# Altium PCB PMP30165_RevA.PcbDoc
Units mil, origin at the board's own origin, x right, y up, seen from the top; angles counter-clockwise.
Board outline 2445.95 x 1141.73 mil, 2 copper layers (Top Layer, Bottom Layer), stack 62 mil thick; 39 components, 20 nets, 97 pads, 20 vias.
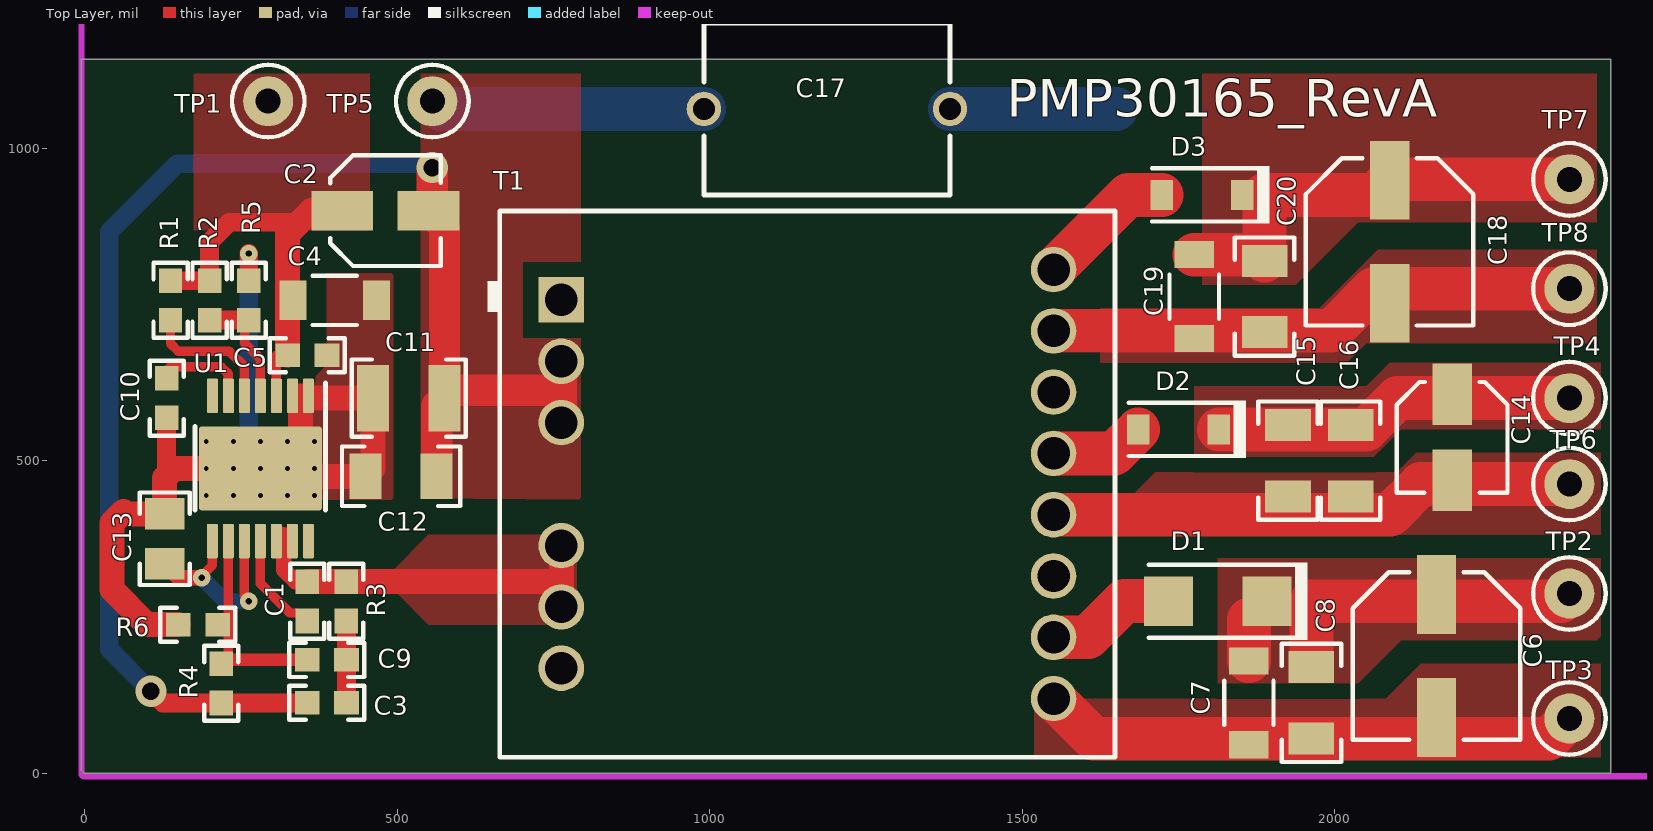
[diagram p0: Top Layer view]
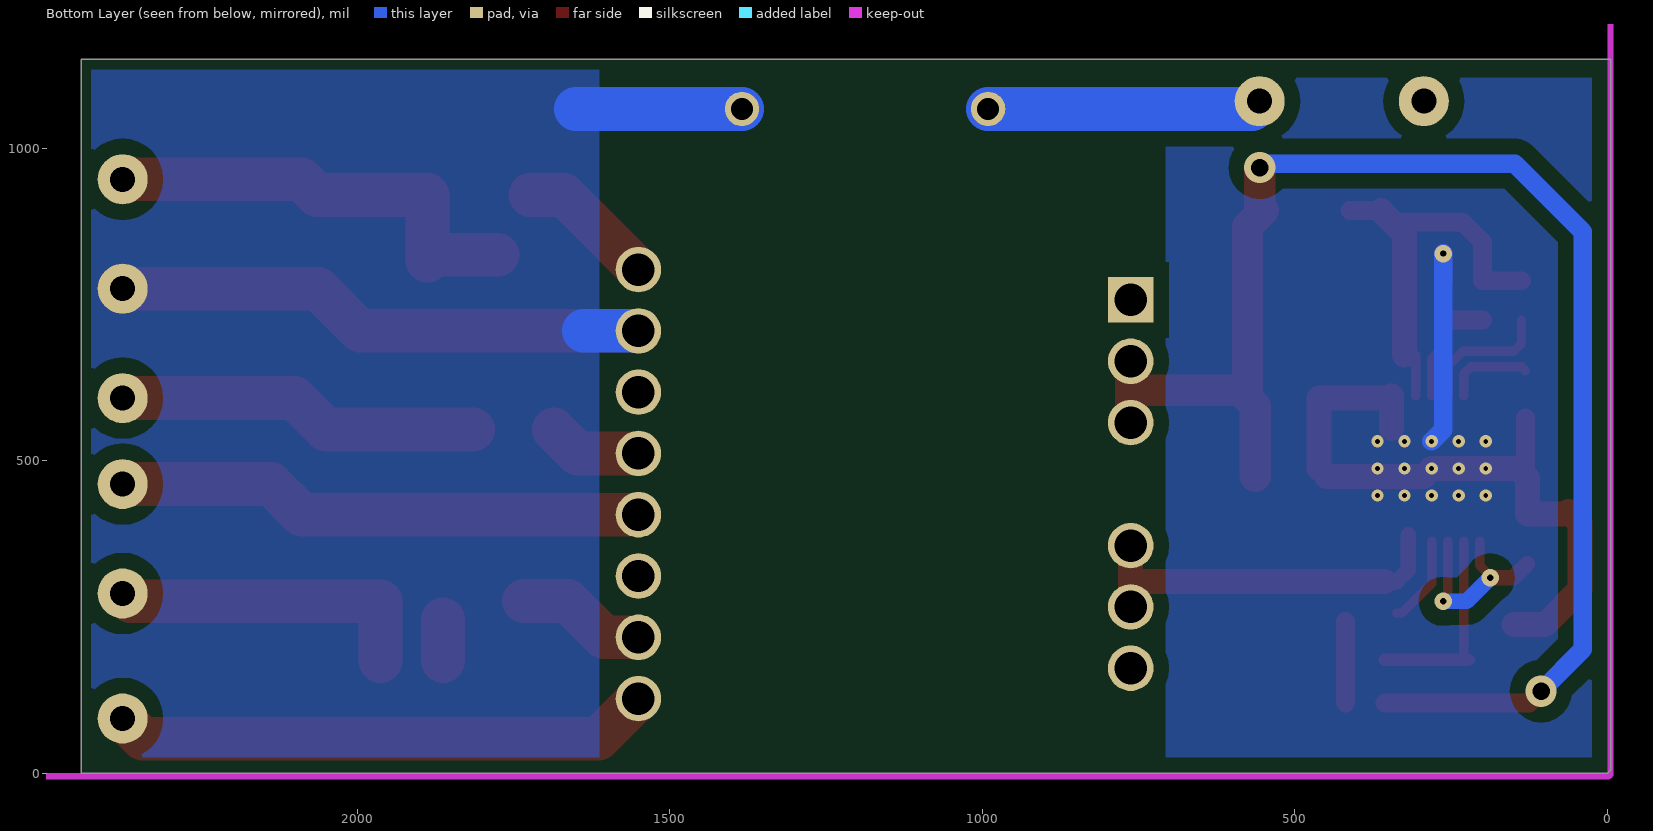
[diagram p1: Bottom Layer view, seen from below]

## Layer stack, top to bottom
Top Solder: solder mask 0.4, Solder Resist, Dk 3.5
Top Layer: signal copper 1.4
Dielectric1: core 59.2, FR-4, Dk 4.8
Bottom Layer: signal copper 1.4
Bottom Solder: solder mask 0.4, Solder Resist, Dk 3.5

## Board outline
0,0 -5,5 -5,1141.73 2440.94,1141.73 2440.94,0

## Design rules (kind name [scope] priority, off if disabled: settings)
AcuteAngle [All] p1: minimum=4.50000000000000E+0001 checktracksonly=FALSE
AssemblyTestPointUsage [All] p1: valid=2
Clearance Clearance_Keepouts [((IsTrack Or IsArc) And Not InPoly) And IsFree and IsKeepOut vs ((IsTrack Or IsArc) And Not InPoly) And IsFree and IsKeepOut] p1: gap=0
Clearance Clearance_BoardEdge_MountingHoles [OnCopper and InComponentClass('Mounting Holes') vs IsKeepOut] p2: gap=20
Clearance Clearance_BoardEdge_Poly [OnCopper and InPoly vs IsKeepOut] p3: gap=25
Clearance Clearance_BoardEdge [OnCopper and Not InComponentClass('Logo') and not InComponentClass('FiducialMark') and not InRegion(1000,500,4000,800) and Not IsKeepout vs IsKeepOut] p4: gap=20
Clearance Clearance_Poly [InPolygon] p5: gap=25
Clearance [All] p6: gap=7.87
ComponentClearance ComponentClearance_MountingHoles_FiducialMarks [InComponentClass('Mounting Holes') vs InComponentClass('FiducialMark')] p1: gap=20 collisioncheckmode=3 verticalgap=10 showdistances=FALSE
ComponentClearance ComponentClearance_Shunt [InComponentClass('Header') vs InComponentClass('Shunt')] p2: gap=0 collisioncheckmode=3 verticalgap=0 showdistances=FALSE
ComponentClearance ComponentClearance_Logo [InComponentClass('Logo')] p3: gap=20 collisioncheckmode=3 verticalgap=10 showdistances=FALSE
ComponentClearance ComponentClearance_ScrewToNut [(HasFootprint('NY PMS 440 0025 PH')) vs (HasFootprint('Keystone_1902C'))] p4: gap=5 collisioncheckmode=3 verticalgap=10 showdistances=FALSE
ComponentClearance ComponentClearance_MountingHoles [InComponentClass('Mounting Holes')] p5: gap=20 collisioncheckmode=3 verticalgap=100000 showdistances=FALSE
ComponentClearance ComponentClearance_SmallPassives [HasFootprint('0201*') or HasFootprint('0402*') or HasFootprint('0508') or HasFootprint('0603*') or HasFootprint('0612') or HasFootprint('0805*') or HasFootprint('0815*') or HasFootprint('0830*') or HasFootprint('1206*') or HasFootprint('1210*') or HasFootprint('1808*') or HasFootprint('1812*') or HasFootprint('1825*') or HasFootprint('2010*') or HasFootprint('2220*') or HasFootprint('2225*') or HasFootprint('2512*') or HasFootprint('2728*') or HasFootprint('3518*') vs HasFootprint('0201*') or HasFootprint('0402*') or HasFootprint('0508') or HasFootprint('0603*') or HasFootprint('0612') or HasFootprint('0805*') or HasFootprint('0815*') or HasFootprint('0830*') or HasFootprint('1206*') or HasFootprint('1210*') or HasFootprint('1808*') or HasFootprint('1812*') or HasFootprint('1825*') or HasFootprint('2010*') or HasFootprint('2220*') or HasFootprint('2225*') or HasFootprint('2512*') or HasFootprint('2728*') or HasFootprint('3518*')] p6: gap=20 collisioncheckmode=3 verticalgap=10 showdistances=FALSE
ComponentClearance ComponentClearance_THtoSMT [IsThruComponent vs IsSMTComponent] p7: gap=20 collisioncheckmode=3 verticalgap=30 showdistances=FALSE
ComponentClearance ComponentClearance_THtoTH [IsThruComponent vs IsThruComponent] p8: gap=20 collisioncheckmode=3 verticalgap=30 showdistances=FALSE
ComponentClearance [All] p9: gap=10 collisioncheckmode=3 verticalgap=10 showdistances=FALSE
DiffPairsRouting [All] p1: maxlimit=100 minlimit=10 mostfreqgap=10 toplayer_minwidth=15 toplayer_maxwidth=15 toplayer_prefwidth=15 bottomlayer_minwidth=15 bottomlayer_maxwidth=15 bottomlayer_prefwidth=15 maxuncoupledlength=1000
FabricationTestPointUsage TestPointUsage [All] p1: valid=2 allowmultiple=FALSE
FabricationTestpoint Testpoint [All] p1: side=3 testpointundercomponent=TRUE minsize=40 maxsize=100 preferedsize=60 minholesize=0 maxholesize=40 preferedholesize=32 testpointgrid=1 allowsidetop=TRUE allowsidebottom=TRUE usegrid=TRUE gridtolerance=0.01
FanoutControl Fanout_LCC [IsLCC] p1: bgadir=Out bgaviamode=Centered fanoutstyle=Auto fanoutdirection=Alternating viagrid=1 // Fanout_LCC (Default Rule)
FanoutControl Fanout_BGA [IsBGA] p2: bgadir=Out bgaviamode=Centered fanoutstyle=Auto fanoutdirection=Alternating viagrid=1 // Fanout_BGA (Default Rule)
FanoutControl Fanout_Default [All] p4: bgadir=Out bgaviamode=Centered fanoutstyle=Auto fanoutdirection=Alternating viagrid=1 // Fanout_Default (Default Rule)
FanoutControl Fanout_Small [(CompPinCount < 5)] p5: bgadir=Out bgaviamode=Centered fanoutstyle=Auto fanoutdirection=OutThenIn viagrid=1 // Fanout_Small (Default Rule)
HoleSize [All] p1: absolutevalues=TRUE maxlimit=251 minlimit=6 maxpercent=80.000 minpercent=20.000
MinimumAnnularRing MinimumAnnularRing_ThermalPadVias [IsVia and InAnyComponent] p1: minimumring=5.91
MinimumAnnularRing [All] p2: minimumring=9
MinimumSolderMaskSliver MinimumSolderMaskSliver_Logo [InComponentClass('Logo') vs InComponentClass('Logo')] p1: minsoldermaskwidth=0.7
MinimumSolderMaskSliver [All] p2: minsoldermaskwidth=3.94
PlaneConnect [All] p1: planeconnectstyle=Relief reliefexpansion=10 reliefentries=4 reliefconductorwidth=10 reliefairgap=10
PolygonConnect [All] p1: connectstyle=Direct reliefconductorwidth=10 reliefentries=4 polygonreliefangle="90 Angle" airgapwidth=10
RoutingVias ThermalPadVias [IsVia and InAnyComponent] p1: holewidth=7.87 width=19.68 viastyle="Through Hole" minholewidth=7.87 minwidth=19.68 maxholewidth=12.99 maxwidth=23.62
RoutingVias [All] p2: holewidth=16 width=34 viastyle="Through Hole" minholewidth=7.87 minwidth=26 maxholewidth=40 maxwidth=65
SilkToBoardRegionClearance [Not ((IsComment or IsDesignator) And (Hide <> 'False')) and not InRegion(1000,500,4000,800)] p1:
SilkToSilkClearance SilkToSilkClearance_Pb-FreeLogo [(HasFootprint('Pb-Free_Overlay_Medium') OR HasFootprint('Pb-Free_Overlay_Small')) vs (HasFootprint('Pb-Free_Overlay_Medium') OR HasFootprint('Pb-Free_Overlay_Small'))] p1: silktosilkclearance=0
SilkToSilkClearance [All] p2: silktosilkclearance=4
SilkToSolderMaskClearance SilkToComonentPadClearance [IsPad and InAnycomponent] p1: minsilkscreentomaskgap=5 clearancetoexposedcopper=TRUE
SilkToSolderMaskClearance "Silk to Solder Mask Opening" [All] p2: minsilkscreentomaskgap=4 clearancetoexposedcopper=FALSE
SolderMaskExpansion [All] p1: expansion=1.97
Width [All] p1: maxlimit=100 minlimit=6 preferedwidth=10 checkconnectedcopper=TRUE
15 further rules are at their usual default settings.

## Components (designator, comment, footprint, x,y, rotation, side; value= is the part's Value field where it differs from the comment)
C1 "C0603C103J5RACTU" 0603 356.25,275 r90 top
C2 "EEE-FK1E100R" SM_RADIAL_B 481.25,900 r0 top
C3 "GRM188R71H222KA01D" 0603 387.5,112.5 r0 top
C4 "C3216X7R1H475K160AC" 1206_180 400,756.25 r0 top
C5 "GRM188R71H104KA93D" 0603 356.25,668.75 r0 top
C6 "DNP" SM_RADIAL_D 2162.5,187.5 r270 top
C7 "GRM31CR71C475KA01L" 1206_180 1862.5,112.5 r270 top
C8 "DNP" 1206 1962.5,112.5 r270 top
C9 "C0603C103J5RACTU" 0603 387.5,181.25 r180 top
C10 "GRM188R71H223KA01D" 0603 131.25,600 r270 top
C11 "GRM32ER71E226KE15L" 1210_270 518.75,600 r180 top
C12 "Used in BOM report" 1206 506.25,475 r180 top
C13 "08055C105KAT2A" 0805_HV 128.12,375 r90 top
C14 "DNP" SM_RADIAL_B 2187.5,537.5 r270 top
C15 "GRM31MR71E225KA93L" 1206 1925,500 r270 top
C16 "DNP" 1206 2025,500 r270 top
C17 "DNP" KX_1000x700 1187.5,1062.5 r180 top
C18 "DNP" SM_RADIAL_D 2087.5,850 r270 top
C19 "GRM31CR71H225KA88L" 1206_180 1775,762.5 r270 top
C20 "DNP" 1206 1887.5,762.5 r270 top
D1 "B130-13-F" SMA 1812.5,275 r180 top
D2 "MBR0540T1G" SOD-123 1750,550 r180 top
D3 "MBR0580-TP" SOD-123 1787.5,925 r180 top
R1 "CRCW0603590KFKEA" 0603 137.5,756.25 r270 top
R2 "CRCW06030000Z0EA" 0603 200,756.25 r90 top
R3 "CRCW0603100KFKEA" 0603 418.75,275 r270 top
R4 "CRCW060349K9FKEA" 0603 218.75,143.75 r270 top
R5 "DNP" 0603 262.5,756.25 r270 top
R6 "CRCW060310K0FKEA" 0603 181.25,237.5 r0 top
T1 "750316586" Wurth_750316586 1156.25,462.5 r0 top
TP1 "5000" Keystone5000 293.75,1075 r0 top
TP2 "5000" Keystone5000 2375,287.5 r0 top
TP3 "5001" Keystone5001 2375,87.5 r0 top
TP4 "5000" Keystone5000 2375,600 r0 top
TP5 "5001" Keystone5001 556.25,1075 r0 top
TP6 "5001" Keystone5001 2375,462.5 r0 top
TP7 "5000" Keystone5000 2375,950 r0 top
TP8 "5001" Keystone5001 2375,775 r0 top
U1 "LM5160QPWPRQ1" PWP0014A_N 281.25,487.5 r270 top

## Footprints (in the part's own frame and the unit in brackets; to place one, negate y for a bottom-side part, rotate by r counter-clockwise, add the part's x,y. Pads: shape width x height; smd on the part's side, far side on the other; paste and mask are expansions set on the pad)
0603 [mm] "0603 from SM-752 data"
  rect 1x0.95 smd: 1(-0.8,0) 2(0.8,0)
  silkscreen extent -1.52,-0.69 1.52,0.69, body extent -0.87,-0.47 0.87,0.47, height 1
0805_HV [mil] "0805 with 30mil clearance between pads"
  rect 50x63 smd: 1(-40,0) 2(40,0)
  silkscreen extent -74,-40 74,40, body extent -43,-29 43,29, height 57
1206 [mm] "1206 from SM-752 data"
  rect 1.3x1.85 smd: 1(-1.45,0) 2(1.45,0)
  silkscreen extent -2.4,-1.21 2.4,1.21, body extent -1.7,-0.9 1.7,0.9, height 1.35
1206_180 [mm] "1206_180"
  rect 1.1x1.6 smd: 1(-1.7,0) 2(1.7,0)
  silkscreen extent -0.9,-1 0.9,1, body extent -1.75,-0.95 1.75,0.95, height 1.8
1210_270 [mm] "1210"
  rect 1.3x2.7 smd: 1(-1.45,0) 2(1.45,0)
  silkscreen extent -2.32,-1.57 2.32,1.57, body extent -1.7,-1.35 1.7,1.35, height 2.7
Keystone5000 [mil] "For Keystone 500x miniature loop terminals"
  round 80 hole 40: 1(0,0)
  silkscreen extent -58,-58 58,58, body extent -49,-49 49,49, height 182
Keystone5001 [mil] "For Keystone 500x miniature loop terminals"
  round 80 hole 40: 1(0,0)
  silkscreen extent -58,-58 58,58, body extent -49,-49 49,49, height 182
KX_1000x700 [mm] "TH, 2-Leads, Dia 10mm, Lead Spacing 10mm"
  round 1.4 hole 0.9: 1(-5,0) 2(5,0)
  silkscreen extent -5,-3.5 5,3.5, body extent -5.32,-3.5 5.33,3.5, height 12.99
PWP0014A_N [mm] "TSOP, 14-Leads, Body 5x4.4mm, Pitch 0.65mm, Thermal Pad 3x3.1 mm, IPC Medium Density"
  rrect22% 1.4x0.45 smd: 1(-2.95,1.95) 2(-2.95,1.3) 3(-2.95,0.65) 4(-2.95,0) 5(-2.95,-0.65) 6(-2.95,-1.3) 7(-2.95,-1.95) 8(2.95,-1.95) 9(2.95,-1.3) 10(2.95,-0.65) 11(2.95,0) 12(2.95,0.65) 13(2.95,1.3) 14(2.95,1.95)
  rrect6% 3.4x5 smd paste-2 mask-2: 15(0,0)
  rrect3% 3.155x3.255 on Top Paste: 15(0,0)
  rrect3% 3.155x3.255 on Top Solder: 15(0,0)
  silkscreen extent -3.47,-2.65 1.7,2.65, body extent -3.21,-2.5 3.21,2.5, height 1
SM_RADIAL_B [mm] "4 x 5.8mm:  Panasonic B"
  rect 2.5x1.6 smd: 1(-1.75,0) 2(1.75,0)
  silkscreen extent -2.24,-2.25 2.25,2.25, body extent -2.25,-2.25 2.25,2.25, height 6.1
SM_RADIAL_D [mm] "6.3 x 5.8mm:  Panasonic D"
  rect 3.2x1.6 smd: 1(-2.5,0) 2(2.5,0)
  silkscreen extent -3.4,-3.4 3.4,3.4, body extent -3.4,-3.4 3.4,3.4, height 6.1
SMA [mm] "Molded Diode, 2-Leads, Body 4.3x2.6mm, IPC Medium Density, based on OnSemi component dimensions and land pattern"
  rect 2x2 smd: 1(-2,0) 2(2,0)
  silkscreen extent -3.66,-1.57 2.79,1.57, body extent -2.6,-1.3 2.6,1.3, height 2.42
SOD-123 [mm] "On Semi recommended land pattern"
  rect 0.915x1.22 smd: 1(-1.637,0) 2(1.637,0)
  silkscreen extent -2.74,-1.17 2.03,1.17, body extent -1.93,-0.9 1.93,0.9, height 1.35
Wurth_750316586 [mm] "TH, 14-Leads, Body 25x22.2mm"
  rect 1.85x1.85 hole 1.32: 1(-10,7.48)
  round 1.85 hole 1.32: 2(-10,4.99) 3(-10,2.5) 4(-10,-2.5) 5(-10,-4.99) 6(-10,-7.48) 7(10,-8.715) 8(10,-6.225) 9(10,-3.735) 10(10,-1.245) 11(10,1.245) 12(10,3.735) 13(10,6.225) 14(10,8.715)
  silkscreen extent -13,-11.1 12.5,11.1, body extent -12.5,-11.1 12.5,11.1, height 16

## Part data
C1 C9: "CAP, CERM, 0.01 µF, 50 V, +/- 5%, X7R, 0603"
C2: "CAP, AL, 10 µF, 25 V, +/- 20%, 1.35 ohm, AEC-Q200 Grade 2, SMD"
C3: "CAP, CERM, 2200 pF, 50 V, +/- 10%, X7R, 0603"
C4: "CAP, CERM, 4.7 µF, 50 V, +/- 10%, X7R, 1206"
C5: "CAP, CERM, 0.1 µF, 50 V, +/- 10%, X7R, 0603"
C6: library part EEE-FK1C470P, "CAP, AL, 47 µF, 16 V, +/- 20%, 0.36 ohm, AEC-Q200 Grade 2, SMD"
C7: "CAP, CERM, 4.7 µF, 16 V, +/- 10%, X7R, 1206"
C8 C12 C16 C20: library part Capacitor, "CAP, CERM, xxxF, xxV, [TempCo], xx%, [PackageReference]"
C10: "CAP, CERM, 0.022 µF, 50 V, +/- 10%, X7R, 0603"
C11: "CAP, CERM, 22 µF, 25 V, +/- 10%, X7R, 1210"
C13: "CAP, CERM, 1 µF, 50 V, +/- 10%, X7R, 0805"
C14: library part EEE-FK1E100R, "CAP, AL, 10 µF, 25 V, +/- 20%, 1.35 ohm, AEC-Q200 Grade 2, SMD"
C15: "CAP, CERM, 2.2 µF, 25 V, +/- 10%, X7R, 1206"
C17: library part DE1E3KX332MN4AP01F, "CAP, CERM, 3300 pF, 300 V, +/- 20%, E, D10xT7mm"
C18: library part EEE-FK1H100P, "CAP, AL, 10 µF, 50 V, +/- 20%, 0.88 ohm, AEC-Q200 Grade 2, SMD"
C19: "CAP, CERM, 2.2 µF, 50 V, +/- 10%, X7R, 1206"
D1: "Diode, Schottky, 30 V, 1 A, SMA"
D2: "Diode, Schottky, 40 V, 0.5 A, SOD-123"
D3: "Diode, Schottky, 80 V, 0.5 A, SOD-123"
R1: "RES, 590 k, 1%, 0.1 W, 0603"
R2: "RES, 0, 5%, 0.1 W, 0603"
R3: "RES, 100 k, 1%, 0.1 W, 0603"
R4: "RES, 49.9 k, 1%, 0.1 W, 0603"
R5: library part Resistor, "RES, xxx ohm, x%, xW, [PackageReference]"
R6: "RES, 10.0 k, 1%, 0.1 W, 0603"
T1: "Transformer, 150 uH, TH"
TP1 TP2 TP4 TP7: "Test Point, Miniature, Red, TH"
TP3 TP5 TP6 TP8: "Test Point, Miniature, Black, TH"
U1: "Wide Input 65-V, 1.5-A Synchronous Buck / Fly-Buck Converter, PWP0014A"

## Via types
v1: diameter 19.68, hole 7.87, Top Layer to Bottom Layer, 9 vias
v2: diameter 19.68, hole 7.87, Top Layer to Bottom Layer, tented both sides, 6 vias
v3: diameter 28, hole 10, Top Layer to Bottom Layer, 3 vias
v4: diameter 50, hole 28, Top Layer to Bottom Layer, 2 vias

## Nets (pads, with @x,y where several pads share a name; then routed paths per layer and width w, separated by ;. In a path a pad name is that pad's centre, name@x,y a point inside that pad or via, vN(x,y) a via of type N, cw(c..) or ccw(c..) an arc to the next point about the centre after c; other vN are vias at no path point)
-12V: C4.2 C5.2 C10.2 C11.2 C12.2 C13.2 R5.1 R6.1 U1.1 U1.2 U1.15@281.25,487.5 | length 1411
  Top Layer w30: 131.25,475 C10.2 ; R5.1 v3(262.5,831.25)
  Top Layer w40: R6.1 100,237.5 43.75,293.75 43.75,400 62.5,418.75 66.25,415 C13.2 128.12,471.88 131.25,475 143.75,487.5 v2(194.64,487.5) v1(237.94,487.5) v1(281.25,487.5) ; U1.15@293.75,475 C12.2 ; U1.15@345.23,551.48 345.23,603.64 ; U1.1@361.66,600 C11.2 C12.2@461.66,487.5
  Bottom Layer w30: v3(262.5,831.25) 262.5,549.56 v1(281.25,530.81)
  other v1: 237.94,444.19 281.25,444.19 324.56,444.19 324.56,487.5 237.94,530.81 324.56,530.81
  other v2: 194.64,444.19 367.86,444.19 367.86,487.5 194.64,530.81 367.86,530.81
GND: C17.1 C18.2 C19.2 C20.2 T1.13 TP8.1 | length 1206.2
  Top Layer w70: T1.13 1995.08,707.58 2062.5,775 TP8.1
  Bottom Layer w70: C17.1 1650,1062.5 ; T1.13 1637.5,707.58
GND1: C14.2 C15.2 C16.2 T1.10 TP6.1 | length 845.4
  Top Layer w70: T1.10 2088.48,413.48 2137.5,462.5 TP6.1
GND2: C6.2 C7.2 C8.2 T1.7 TP3.1 | length 865.2
  Top Layer w70: T1.7 1614.34,55 2342.5,55 TP3.1
NetC1_1: C1.1 U1.11 | length 143.7
  Top Layer w15: U1.11 281.25,303.54 328.54,256.25 337.5,256.25
NetC1_2: C1.2 R3.1 T1.4 T1.5 U1.12 U1.13 | length 606.3
  Top Layer w25: 318.75,381.25 318.75,325 337.25,306.5 C1.2
  Top Layer w40: C1.2 761.03,306.5 762.5,305.03 ; T1.5 T1.4
NetC2_1: C2.1 C4.1 C5.1 R1.1 R2.2 TP1.1 U1.3 | length 637
  Top Layer w15: U1.3 C5.1@306.84,668.75
  Top Layer w30: R1.1 R2.2 200,850 231.25,881.25 337.5,881.25 ; 362.5,900 C2.1
  Top Layer w40: C5.1 324.75,862.25 362.5,900
NetC3_2: C3.2 C9.1 R3.2 | length 130.8
  Top Layer w30: C3.2 R3.2@419,243.26
NetC6_1: C6.1 C7.1 C8.1 D1.1 TP2.1 | length 580.1
  Top Layer w70: C7.1 D1.1@1862.5,246.26 ; C8.1@1962.5,179.43 1962.5,275 2362.5,275 TP2.1
NetC9_2: C9.2 R4.1 R6.2 U1.9 | length 324.5
  Top Layer w15: R4.1@230.07,181.25 U1.9
  Top Layer w20: R4.1@221.63,181.25 230.07,181.25 C9.2
NetC10_1: C10.1 U1.6 | length 141
  Top Layer w15: C10.1@131.25,644 137.25,650 218.75,650 230.07,638.68 U1.6
NetC13_1: C13.1 U1.8 U1.10 | length 300.5
  Top Layer w15: v3@193.75,321.88 204.48,332.6 U1.8 ; v3@255.66,284.04 U1.10
  Top Layer w25: C13.1 150.63,312.5 v3(187.5,312.5)
  Bottom Layer w25: v3(187.5,312.5) 225,275 v3(262.5,275)
NetC14_1: C14.1 C15.1 C16.1 D2.1 TP4.1 | length 591.3
  Top Layer w50: C16.1@2017.91,550 C16.1
  Top Layer w70: D2.1 2017.91,550 2050,550 2100,600 TP4.1
NetC18_1: C18.1 C19.1 C20.1 D3.1 TP7.1 | length 705.9
  Top Layer w70: C19.1 C20.1@1877.66,829.43 ; C20.1 1887.5,925 2064.07,925 C18.1 2089.07,950 TP7.1
NetD1_2: D1.2 T1.8 | length 208.1
  Top Layer w50: D1.2@1733.17,275.59 D1.2
  Top Layer w70: T1.8 1604.92,217.42 1663.09,275.59 D1.2@1733.17,275.59
NetD2_2: D2.2 T1.11 | length 151.5
  Top Layer w70: T1.11 1647.05,511.52 D2.2
NetD3_2: D3.2 T1.14 | length 222.5
  Top Layer w70: T1.14 1669.34,925 D3.2
NetR1_2: R1.2 U1.5 | length 217.7
  Top Layer w15: R1.2 137.5,687.5 150,675 231.25,675 255.66,650.59 U1.5
NetR2_1: R2.1 R5.2 U1.4 | length 181.7
  Top Layer w15: R5.2@256.25,712.5 256.25,687.5 281.25,662.5 U1.4
  Top Layer w30: R2.1 R5.2
PGND: C2.2 C3.1 C11.1 C12.1 C17.2 R4.2 T1.2 T1.3 TP5.1 | length 2782.2
  Top Layer w30: v4(106.25,131.25) 125,112.5 218.5,112.5 R4.2 ; R4.2@219,112.5 C3.1
  Top Layer w50: C2.2 575.84,874.31 C11.1 ; C2.2@556.25,906.1 v4(556.25,968.75) ; C12.1 C11.1@563.34,587.5 ; C11.1@588.29,612.45 762.55,612.45 ; T1.3 762.55,612.45 ; T1.2 762.55,612.45
  Bottom Layer w30: v4(106.25,131.25) 39.37,198.13 39.37,866.14 148.23,975 550,975 v4(556.25,968.75)
  Bottom Layer w70: TP5.1 568.75,1062.5 C17.2
pads on no net: T1.1 T1.6 T1.9 T1.12 U1.7 U1.14 U1.15@281.25,487.5

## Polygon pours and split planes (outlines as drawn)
NetC2_1 on Top Layer "Top Layer-No Net 3" (solid, pour order 12): 456.25,868.75 175,868.75 175,1118.75 456.25,1118.75
PGND on Top Layer "Top Layer-No Net 1" (solid, pour order 10): 537.5,439.57 537.5,1118.75 793.75,1118.75 793.75,437.5
NetC1_2 on Top Layer "Top Layer-No Net 2" (solid, pour order 8): 787.5,237.5 550,237.5 500,287.5 493.75,287.5 493.75,325 550,381.25 787.5,381.25
-12V on Top Layer "Top Layer-No Net" (solid, pour order 0): 387.5,799.92 387.5,653.37 328.1,593.97 331.25,590.82 331.25,437.5 491.68,437.5 493.75,439.57 493.75,800
NetC18_1 on Top Layer "Top Layer-No Net 6" (solid, pour order 22): 1787.5,1118.75 1787.5,781.25 1918.75,781.25 1937.5,781.25 2037.5,881.25 2418.75,881.25 2418.75,1118.75
NetC6_1 on Top Layer "Top Layer-No Net 4" (solid, pour order 24): 1812.5,343.75 2425,343.75 2425,218.75 2418.75,212.5 2125,212.5 2106.25,212.5 2037.5,143.75 1812.5,143.75
NetC14_1 on Top Layer "Top Layer-No Net 5" (solid, pour order 26): 1775,618.75 2050,618.75 2087.5,656.25 2425,656.25 2425,550 2112.5,550 2106.25,550 2062.5,506.25 1775,506.25
GND2 on Top Layer "Top Layer-No Net 7" (solid, pour order 28): 1518.75,118.75 2081.25,118.75 2137.5,175 2143.75,175 2425,175 2425,18.01 1518.75,18.01
GND1 on Top Layer "Top Layer-No Net 8" (solid, pour order 30): 1681.25,450 1712.5,481.25 1756.25,481.25 2098.92,481.25 2130.17,512.5 2162.5,512.5 2425,512.5 2425,381.25 1681.25,381.25
GND on Top Layer "Top Layer-No Net 9" (solid, pour order 32): 1625,743.75 1968.75,743.75 1975,743.75 2068.75,837.5 2418.75,837.5 2418.75,687.5 2056.25,687.5 2050,687.5 2018.75,656.25 1625,656.25
-12V on Bottom Layer "Bottom Layer-No Net" (solid, pour order 14): 18.75,1112.5 18.75,25 700,25 706.25,18.75 706.25,925 706.25,1112.5
GND on Bottom Layer "Bottom Layer-No Net 1" (solid, pour order 16): 1612.5,1125 2425,1125 2425,12.5 1612.5,12.5

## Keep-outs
Keep-Out Layer:
  lines w10: -5,0 ccw(c0,0) 0,-5 ; -5,0 ccw(c0,0) 0,-5 ; -5,0 -5,3450 ; -5,3450 cw(c0,3450) 0,3455 ; -5,3450 cw(c0,3450) 0,3455 ; 0,-5 4950,-5 ; 0,3455 4950,3455 ; 4950,-5 ccw(c4950,0) 4955,0 ; 4950,-5 ccw(c4950,0) 4955,0 ; 4950,3455 cw(c4950,3450) 4955,3450 ; 4950,3455 cw(c4950,3450) 4955,3450 ; 4955,0 4955,3450
  text ".Layer_Name" at 577,-858.49 h60

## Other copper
Top Layer:
  text ".Layer_Name" at 577,-858.49 h60
Bottom Layer:
  text ".Layer_Name" at 577,-858.49 h60

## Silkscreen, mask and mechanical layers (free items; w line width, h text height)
Top Overlay:
  text "PMP30165_RevA" at 1475,1050 h60
  text ".Layer_Name" at 577,-858.49 h30
Bottom Overlay:
  text ".Layer_Name" at 577,-858.49 h60
Top Paste:
  text ".Layer_Name" at 577,-858.49 h60
Bottom Paste:
  text ".Layer_Name" at 577,-858.49 h60
Top Solder:
  text ".Layer_Name" at 577,-858.49 h60
  text ".Layer_Name" at 577,-858.49 h60
Bottom Solder:
  text ".Layer_Name" at 577,-858.49 h60
Drill Guide:
  text ".Layer_Name" at 577,-858.49 h60
M1 Board Outline:
  the board outline again, w10
  text ".Layer_Name" at 577,-858.49 h60
M2 Board Dimensions:
  rectangle: 0,-275 125,-150
  rectangle: 125,-400 500,-275
  lines w7: 0,-275 1000,-275 ; 125,-400 125,-150 ; 250,-400 250,-150 ; 500,-400 500,-150 ; 750,-400 750,-150 ; 0,-400 1000,-400 1000,-150 0,-150 0,-400
  text ".Layer_Name" at 577,-858.49 h60
M3 3D STEP Top:
  text ".Layer_Name" at 577,-858.49 h60
M4 3D STEP Bottom:
  text ".Layer_Name" at 577,-858.49 h60
M5 Assembly Top:
  lines w10: -292,-930.17 6308,-930.17 ; -292,-726.83 6310,-726.83 ; -292,-523.5 -292,-1133.5 3713,-1133.5 6310,-1133.5 6310,-523.5 -291.5,-523.5 -291.5,-1133.5 1284,-1133.5 ; 2173,-1133.5 2173,-523.5 ; 3440,-726.83 3440,-523.5 ; 4280,-726.83 4280,-523.5 ; 4902,-1140 4902,-937.17
  text "COMPONENTS MARKED 'DNP' SHOULD NOT BE POPULATED." at 1153.5,-318.5 h60
  text "PCB VIEWED FROM TOP SIDE" at -228.5,-655.67 h60
  text "BOARD #:" at 2248,-655.67 h60
  text ".PRJ_Number" at 2793.5,-655.67 h60
  text "REV:" at 3638,-655.67 h60
  text ".PCB_Rev" at 3929.5,-655.67 h60
  text "SVN REV:" at 4476,-655.67 h60
  text ".VersionControl_RevNumber" at 4982,-655.67 h60
  text "TID #:" at 2248,-859 h60
  text ".TID" at 2793.5,-859 h60
  text "PLOT NAME =" at -228.5,-1064.34 h60
  text ".plot_File_Name" at 577,-1064.34 h60
  text "GENERATED    :" at 2250,-1064.34 h60
  text ".Print_Date" at 3119.5,-1064.34 h60
  text ".Print_Time" at 3848.5,-1064.34 h60
  text "TEXAS INSTRUMENTS" at 5113,-1064.34 h60
M6 Assembly Bottom:
  lines w10: -292.5,-727.33 6309.5,-727.33 ; -290.5,-930.67 6309.5,-930.67 ; 1115.5,-1140.5 1115.5,-937.67 ; 1737.5,-727.33 1737.5,-524 ; 2577.5,-727.33 2577.5,-524 ; 3844.5,-1134 3844.5,-524 ; 4733.5,-1134 6309,-1134 6309,-524 -292.5,-524 -292.5,-1134 2304.5,-1134 6309.5,-1134 6309.5,-524
  text ".VersionControl_RevNumber" at 1035.5,-656.17 h60
  text "SVN REV:" at 1541.5,-656.17 h60
  text ".PCB_Rev" at 2088,-656.17 h60
  text "REV:" at 2379.5,-656.17 h60
  text ".PRJ_Number" at 3224,-656.17 h60
  text "BOARD #:" at 3769.5,-656.17 h60
  text "PCB VIEWED FROM BOTTOM SIDE" at 6246,-656.17 h60
  text ".TID" at 3224,-859.5 h60
  text "TID #:" at 3769.5,-859.5 h60
  text "TEXAS INSTRUMENTS" at 904.5,-1064.84 h60
  text ".Print_Time" at 2169,-1064.84 h60
  text ".Print_Date" at 2898,-1064.84 h60
  text "GENERATED    :" at 3767.5,-1064.84 h60
  text ".plot_File_Name" at 5440.5,-1064.84 h60
  text "PLOT NAME =" at 6246,-1064.84 h60
M9 Title Sheet:
  drawing of 57 lines, arcs and shapes, not listed
  text "1" at 739.84,8036.5 h70
  text "2" at 3235.5,8036.5 h70
  text "3" at 5724.84,8036.5 h70
  text "4" at 8231.51,8036.5 h70
  text "5" at 10730.5,8036.5 h70
  text "6" at 13235.5,8036.5 h70
  text "A" at -416.5,6893.5 h70
  text "A" at 14383.5,6893.5 h70
  text "B" at -416.5,4513.5 h70
  text "B" at 14383.5,4513.5 h70
  text "C" at -416.5,2138.5 h70
  text "C" at 14383.5,2138.5 h70
  text "PROJECT TITLE:" at 11343.5,277.5 h45
  text ".PRJ_Title" at 11393.5,144.17 h70
  text "DESIGNED FOR:" at 11343.5,-23.5 h45
  text ".PRJ_Customer" at 11393.5,-163.5 h70
  text "D" at -416.5,-231.5 h70
  text "D" at 14383.5,-231.5 h70
  text "FILE NAME:" at 11343.5,-323.5 h45
  text ".PCB_File_Name_No_Path" at 11393.5,-443.5 h70
  text "Texas Instruments (TI) and/or its licensors do not warrant the accuracy or completeness of this specification" at 6374,-605.34 h45
  text "ENGINEER:" at 11343.5,-613.5 h45
  text "LAYOUT BY:" at 12848.5,-613.5 h45
  text "or any information contained therein. TI and/or its licensors do not warrant that this design will meet" at 6329.01,-718 h45
  text ".PRJ_Engineer" at 11393.5,-768.49 h70
  text ".PCB_Layout" at 12899,-768.49 h70
  text "the specifications, will be suitable for your application or fit for any particular purpose, or will operate in" at 6329.01,-830.67 h45
  text ".Layer_Name" at 577,-858.49 h60
  text "ALTIUM DESIGNER VERSION:" at 12848.5,-923.5 h45
  text "an implementation. TI and/or its licensors do not warrant that the design is production worthy. You should" at 6329.01,-943.33 h45
  text "completely validate and test your design implementation to confirm the system functionality for your application." at 6374,-1056 h45
  text ".print_Scale" at 11393.5,-1056.83 h70
  text ".Application_BuildNumber" at 12899,-1056.83 h70
  text "1" at 739.84,-1263.5 h70
  text "2" at 3235.5,-1263.5 h70
  text "3" at 5724.84,-1263.5 h70
  text "4" at 8231.51,-1263.5 h70
  text "5" at 10730.5,-1263.5 h70
  text "6" at 13235.5,-1263.5 h70
M10 Fab Notes:
  drawing of 173 lines, arcs and shapes, not listed
  text "DESIGN INFORMATION" at 12377.02,6201 h60
  text "MIN. TRACK WIDTH:" at 11732.46,6021 h60
  text "8" at 12828.7,6021 h60
  text "MIL" at 12983.46,6021 h60
  text "MIN. CLEARANCE:" at 11732.46,5889 h60
  text "0.2" at 12768.7,5889 h60
  text "mm" at 12983.46,5889 h60
  text "MIN. VIA PAD SIZE:" at 11732.46,5757 h60
  text "24" at 12798.71,5757 h60
  text "MIL" at 12983.46,5757 h60
  text "0.05mm (2MIL)" at 12427.46,5615.29 h60
  text "MINIMUM ANNULAR RING" at 11403.23,5611 h60
  text "EXTERNAL" at 13135.46,5611 h60
  text "PER" at 11603.23,5493 h60
  text "IPC-D-275 CLASS 2 LEVEL C" at 11823.23,5493 h60
  text "MIL, HOLES" at 13311.46,5380.71 h60
  text "+/-" at 12919,5380 h60
  text "+/-" at 13773,5380 h60
  text "REGISTRATION TOLERANCES:" at 11403.23,5375 h60
  text "METAL" at 12603,5375 h60
  text "5" at 13179.2,5375 h60
  text "3" at 14012.2,5375 h60
  text "MIL" at 14128.46,5375 h60
  text "+/-" at 13773,5262 h60
  text "HOLE SIZE TOLERANCE (UNLESS OTHERWISE SPECIFIED):" at 11403.23,5257 h60
  text "3" at 14012.2,5257 h60
  text "MIL" at 14128.46,5257 h60
  text "MATERIAL:" at 11328.46,5047.54 h60
  text "FR-4 High Tg" at 12314.9,4907.21 h60
  text "FR-408" at 11749.46,4898.64 h60
  text "OTHER" at 13237.46,4898.64 h60
  text "X" at 12160,4895 h60
  text "62 MIL (1.6mm) +/-10%" at 12069.56,4735.92 h60
  text "THICKNESS:" at 11403.23,4731.64 h60
  text "X" at 11941.4,4731.64 h60
  text "OTHER" at 13354.46,4731.64 h60
  text "TOLERANCE:" at 11403.23,4573.64 h60
  text "X" at 12242.53,4573.64 h60
  text "ANSI IPC-6012 TYPE 3 CLASS 2" at 12429.48,4573.64 h60
  text "OTHER +/-" at 12429.46,4417.64 h60
  text "BOW & TWIST:" at 11403.23,4260.64 h60
  text "X" at 12242.53,4260.64 h60
  text "ANSI IPC-6012 TYPE 3 CLASS 2" at 12429.48,4260.64 h60
  text "OTHER +/-" at 12429.46,4102.13 h60
  text "DRILLING:" at 11328.46,3963.64 h60
  text "REFERENCE:" at 11403.23,3846.64 h60
  text "X" at 12051.46,3846.64 h60
  text "AS SHOWN" at 12238.46,3846.64 h60
  text "X" at 12952.46,3846.64 h60
  text "NC_DRILL FILES" at 13089.46,3846.64 h60
  text "PTH COPPER THICKNESS:" at 11403.23,3688.64 h60
  text "X" at 12533.46,3688.64 h60
  text "20-30 um" at 12670.46,3688.64 h60
  text "OTHER" at 13387.46,3688.64 h60
  text "BOARD FINISH:" at 11328.46,3529.64 h60
  text "SILKSCREEN:" at 11483.68,3411.64 h60
  text "X" at 12432.46,3411.64 h60
  text "TOP" at 12558.46,3411.64 h60
  text "X" at 12942.46,3411.64 h60
  text "BOTTOM" at 13069.46,3411.64 h60
  text "SILKSCREEN COLOR:" at 11483.68,3244.64 h60
  text "X" at 12431.42,3244.64 h60
  text "WHITE" at 12558.46,3244.64 h60
  text "OTHER" at 13069.46,3244.64 h60
  text "X" at 12562.42,3085.44 h60
  text "GREEN" at 12689.46,3085.44 h60
  text "OTHER" at 13307.46,3085.44 h60
  text "SOLDER RESIST COLOR:" at 11483.68,3074.64 h60
  text "X" at 12562.42,2915.44 h60
  text "MATTE" at 12689.46,2915.44 h60
  text "SEMI-GLOSS" at 13307,2914.8 h60
  text "IMMERSION GOLD (ENIG)" at 12389.46,2726.92 h60
  text "ENEPIG" at 13727,2723.64 h60
  text "SURFACE FINISH:" at 11328.46,2722.64 h60
  text "X" at 12202.51,2722.64 h60
  text "IMM. TIN/SILVER OR EQUIV" at 11658,2565.64 h60
  text "OTHER" at 13089.46,2565.64 h60
  text "ARRAY/PANEL:" at 11328.46,2386.64 h60
  text "CUT AND TRIM PER M1 BOARD OUTLINE" at 12389.46,2382.35 h60
  text "N.C. ROUTE" at 12389.46,2230.64 h60
  text "X" at 13068.46,2230.64 h60
  text "V. SCORE" at 13255.46,2230.64 h60
  text "CERTIFICATION:" at 11328.46,2093.64 h60
  text "MATERIALS AND WORKMANSHIP FOR ALL PCBS" at 12053.46,2093.64 h60
  text "TO MEET OR EXCEED THE REQUIREMENTS OF:" at 12053.46,1995.64 h60
  text "X" at 11679.96,1859.13 h60
  text "ANSI IPC-A-600F CLASS ->" at 11818.96,1859.13 h60
  text "X" at 13458.02,1859.13 h60
  text "2" at 13576.96,1859.14 h60
  text "1" at 13261.96,1857.64 h60
  text "3" at 13930.96,1857.64 h60
  text "X" at 12494.02,1699.64 h60
  text "RoHS" at 12630.96,1699.64 h60
  text "OTHER" at 13275.36,1699.64 h60
  text "PER ORDER" at 13672.42,1699.64 h60
  text "ALL BOARDS MUST MEET OR EXCEED UL94-V0 REQUIREMENTS." at 11356,1534 h60
  text "PCB MUST BEAR THE UL94V-0 UL REGISTERED MATERIAL ID NUMBER" at 11356,1414 h60
  text "ADDITIONAL REQUIREMENTS:" at 11328.46,1240.64 h60
  text "MICROSECTION:" at 11403.23,1125.64 h60
  text "YES" at 12308.96,1125.64 h60
  text "REQUIRED" at 13170.46,969.49 h60
  text "BARE BOARD ELEC. TEST:" at 11403.23,966.64 h60
  text "NONE" at 12708.96,966.64 h60
  text "X" at 13043.46,966.64 h60
  text "PER ORDER" at 13762.46,966.64 h60
  text ".Layer_Name" at 577,-858.49 h60
M11 Gerber Information:
  lines w10: -292,-930.17 6308,-930.17 ; -292,-726.83 6310,-726.83 ; -292,-523.5 -292,-1133.5 3713,-1133.5 6310,-1133.5 6310,-523.5 -291.5,-523.5 -291.5,-1133.5 1284,-1133.5 ; 2173,-1133.5 2173,-523.5 ; 3440,-726.83 3440,-523.5 ; 4280,-726.83 4280,-523.5 ; 4902,-1140 4902,-937.17
  text "ALL ARTWORK VIEWED FROM TOP SIDE" at -228.5,-655.67 h60
  text "BOARD #:" at 2248,-655.67 h60
  text ".PRJ_Number" at 2793.5,-655.67 h60
  text "REV:" at 3638,-655.67 h60
  text ".PCB_Rev" at 3929.5,-655.67 h60
  text "SVN REV:" at 4476,-655.67 h60
  text ".VersionControl_RevNumber" at 4982,-655.67 h60
  text "LAYER NAME =" at -228.5,-858.49 h60
  text "TID #:" at 2248,-859 h60
  text ".TID" at 2793.5,-859 h60
  text "PLOT NAME =" at -228.5,-1064.34 h60
  text ".plot_File_Name" at 577,-1064.34 h60
  text "GENERATED    :" at 2250,-1064.34 h60
  text ".Print_Date" at 3119.5,-1064.34 h60
  text ".Print_Time" at 3848.5,-1064.34 h60
  text "TEXAS INSTRUMENTS" at 5113,-1064.34 h60
M12 Stackup:
  drawing of 191 lines, arcs and shapes, not listed
  text "Layer" at 9790.58,7830 h60
  text "Name" at 10200.49,7830 h60
  text "Material" at 11130.23,7830 h60
  text "Thickness" at 11990,7830 h60
  text "Constant" at 12639.84,7830 h60
  text "Board Layer Stack" at 13209.7,7830 h60
  text "1" at 9790.58,7710 h60
  text "Top Overlay" at 10200.49,7710 h60
  text "2" at 9790.58,7590 h60
  text "Top Solder" at 10200.49,7590 h60
  text "Solder Resist" at 11130.23,7590 h60
  text "0.40mil" at 11990,7590 h60
  text "3.5" at 12639.84,7590 h60
  text "3" at 9790.58,7470 h60
  text "Top Layer" at 10200.49,7470 h60
  text "Copper" at 11130.23,7470 h60
  text "1.40mil" at 11990,7470 h60
  text "4" at 9790.58,7350 h60
  text "Dielectric1" at 10200.49,7350 h60
  text "FR-4" at 11130.23,7350 h60
  text "59.20mil" at 11990,7350 h60
  text "4.8" at 12639.84,7350 h60
  text "5" at 9790.58,7230 h60
  text "Bottom Layer" at 10200.49,7230 h60
  text "Copper" at 11130.23,7230 h60
  text "1.40mil" at 11990,7230 h60
  text "6" at 9790.58,7110 h60
  text "Bottom Solder" at 10200.49,7110 h60
  text "Solder Resist" at 11130.23,7110 h60
  text "0.40mil" at 11990,7110 h60
  text "3.5" at 12639.84,7110 h60
  text "7" at 9790.58,6990 h60
  text "Bottom Overlay" at 10200.49,6990 h60
  text ".Layer_Name" at 577,-858.49 h60
M13 Component Bodies Top:
  text ".Layer_Name" at 577,-858.49 h60
M14 Component Bodies Bottom:
  text ".Layer_Name" at 577,-858.49 h60
M15 Courtyards Top:
  text ".Layer_Name" at 577,-858.49 h60
M16 Courtyards Bottom:
  text ".Layer_Name" at 577,-858.49 h60
Drill Drawing:
  text ".Layer_Name" at 577,-858.49 h60

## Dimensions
0,-400 to 1000,-400 on M2 Board Dimensions
0,0 to 2440.94,1141.73 on M2 Board Dimensions
0,0 to 2440.94,-39.37 on M2 Board Dimensions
